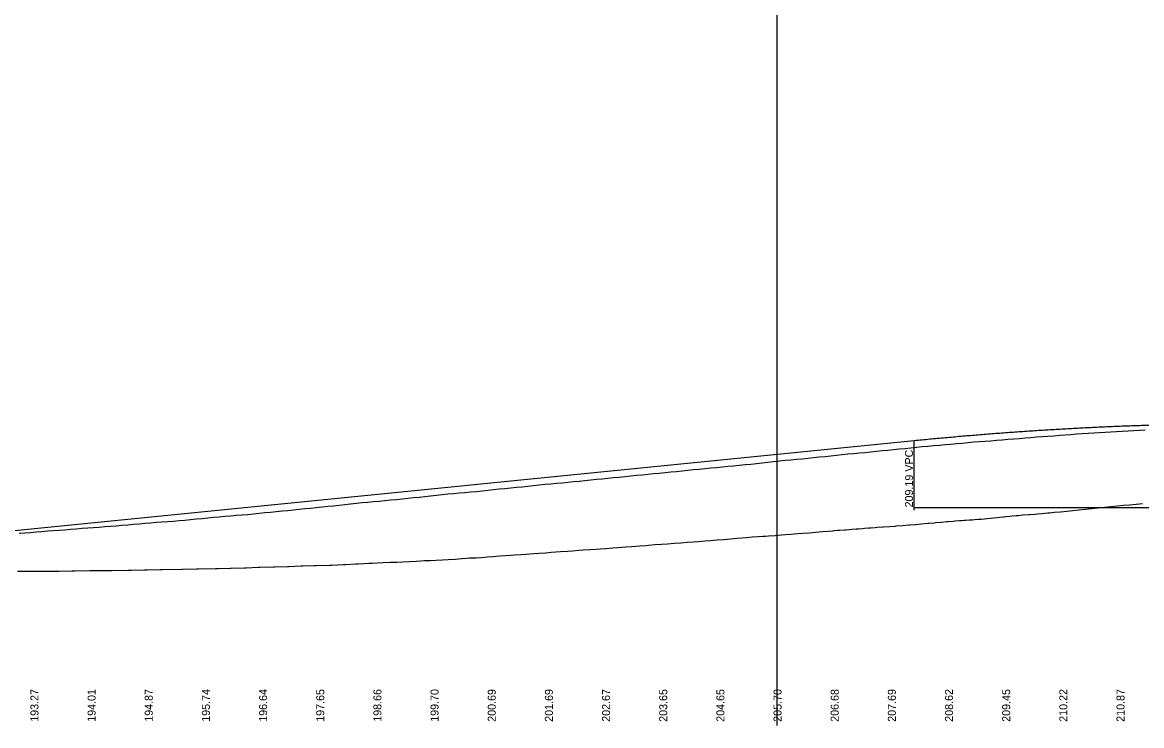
# Model space of a CAD drawing. Extents: x 1838386 to 1955906, y 719739 to 834437.
# Drawn here: x 1880098 to 1881077, y 820597 to 821212 of the extents above; entities that cross this region are included whole.
import ezdxf

# ---------------------------------------------------------------- set-up
doc = ezdxf.new("R2010")
doc.units = 0
for name, color, linetype in [('RD_DDB_Profile_EX', 7, 'Continuous'), ('RD_DDB_Profile_PR', 7, 'Continuous'), ('RD_DDB_StripGrade', 7, 'Continuous'), ('RD_DDB_VCLbl', 7, 'Continuous'), ('RD_Sketch1', 7, 'Continuous')]:
    doc.layers.add(name, color=color, linetype=linetype)

msp = doc.modelspace()

# ---------------------------------------------------------------- linework, layer by layer
at = {"layer": 'RD_DDB_Profile_EX'}
for points in [[(1880890.15, 820841.17), (1880895.15, 820841.68), (1880900.15, 820842.15), (1880905.15, 820842.53), (1880910.15, 820842.97), (1880915.15, 820843.44), (1880920.15, 820843.9), (1880925.15, 820844.37), (1880930.15, 820844.82), (1880935.15, 820845.12), (1880940.15, 820845.5), (1880945.15, 820845.91), (1880950.15, 820846.31), (1880955.15, 820846.72), (1880960.15, 820847.14), (1880965.15, 820847.57), (1880970.15, 820847.99), (1880975.15, 820848.37), (1880980.15, 820848.78), (1880985.15, 820849.2), (1880990.15, 820849.58), (1880995.15, 820849.94), (1881000.15, 820850.31), (1881005.15, 820850.69), (1881010.15, 820851.05), (1881015.15, 820851.38), (1881020.15, 820851.82), (1881025.15, 820852.16), (1881030.15, 820852.46), (1881035.15, 820852.75), (1881040.15, 820853.06), (1881045.15, 820853.38), (1881050.15, 820853.72), (1881055.15, 820854.04), (1881060.15, 820854.29), (1881065.15, 820854.57), (1881070.15, 820854.91), (1881075.15, 820855.23), (1881080.15, 820855.49)], [(1880390.15, 820791.24), (1880395.15, 820791.81), (1880400.15, 820792.29), (1880405.15, 820792.69), (1880410.15, 820793.14), (1880415.15, 820793.65), (1880420.15, 820794.18), (1880425.15, 820794.64), (1880430.15, 820795.15), (1880435.15, 820795.69), (1880440.15, 820796.18), (1880445.15, 820796.67), (1880450.15, 820797.2), (1880455.15, 820797.75), (1880460.15, 820798.29), (1880465.15, 820798.83), (1880470.15, 820799.36), (1880475.15, 820799.82), (1880480.15, 820800.24), (1880485.15, 820800.68), (1880490.15, 820801.15), (1880495.15, 820801.65), (1880500.15, 820802.2), (1880505.15, 820802.76), (1880510.15, 820803.28), (1880515.15, 820803.79), (1880520.15, 820804.25), (1880525.15, 820804.74), (1880530.15, 820805.22), (1880535.15, 820805.71), (1880540.15, 820806.23), (1880545.15, 820806.81), (1880550.15, 820807.35), (1880555.15, 820807.84), (1880560.15, 820808.3), (1880565.15, 820808.73), (1880570.15, 820809.23), (1880575.15, 820809.71), (1880580.15, 820810.19), (1880585.15, 820810.67), (1880590.15, 820811.19), (1880595.15, 820811.72), (1880600.15, 820812.18), (1880605.15, 820812.63), (1880610.15, 820813.18), (1880615.15, 820813.71), (1880620.15, 820814.16), (1880625.15, 820814.64), (1880630.15, 820815.16), (1880635.15, 820815.69), (1880640.15, 820816.2), (1880645.15, 820816.68), (1880650.15, 820817.16), (1880655.15, 820817.62), (1880660.15, 820818.12), (1880665.15, 820818.59), (1880670.15, 820819.1), (1880675.15, 820819.7), (1880680.15, 820820.28), (1880685.15, 820820.82), (1880690.15, 820821.18), (1880695.15, 820821.59), (1880700.15, 820822.15), (1880705.15, 820822.63), (1880710.15, 820823.13), (1880715.15, 820823.58), (1880720.15, 820824.07), (1880725.15, 820824.54), (1880730.15, 820825.08), (1880735.15, 820825.53), (1880740.15, 820826.04), (1880745.15, 820826.62), (1880750.15, 820827.13), (1880755.15, 820827.65), (1880760.15, 820828.26), (1880765.15, 820828.84), (1880770.15, 820829.32), (1880775.15, 820829.66), (1880780.15, 820830.21), (1880785.15, 820830.71), (1880790.15, 820831.21), (1880795.15, 820831.71), (1880800.15, 820832.21), (1880805.15, 820832.71), (1880810.15, 820833.2), (1880815.15, 820833.74), (1880820.15, 820834.32), (1880825.15, 820834.79), (1880830.15, 820835.24), (1880835.15, 820835.74), (1880840.15, 820836.25), (1880845.15, 820836.74), (1880850.15, 820837.24), (1880855.15, 820837.76), (1880860.15, 820838.27), (1880865.15, 820838.78), (1880870.15, 820839.25), (1880875.15, 820839.72), (1880880.15, 820840.22), (1880885.15, 820840.73), (1880890.15, 820841.17)], [(1880095.15, 820764.97), (1880100.15, 820765.39), (1880105.15, 820765.8), (1880110.15, 820766.25), (1880115.15, 820766.62), (1880120.15, 820766.97), (1880125.15, 820767.36), (1880130.15, 820767.74), (1880135.15, 820768.12), (1880140.15, 820768.56), (1880145.15, 820768.99), (1880150.15, 820769.34), (1880155.15, 820769.62), (1880160.15, 820769.92), (1880165.15, 820770.34), (1880170.15, 820770.76), (1880175.15, 820771.13), (1880180.15, 820771.55), (1880185.15, 820772.04), (1880190.15, 820772.49), (1880195.15, 820772.9), (1880200.15, 820773.3), (1880205.15, 820773.77), (1880210.15, 820774.24), (1880215.15, 820774.64), (1880220.15, 820775.01), (1880225.15, 820775.32), (1880230.15, 820775.65), (1880235.15, 820776.06), (1880240.15, 820776.51), (1880245.15, 820777.01), (1880250.15, 820777.53), (1880255.15, 820778.04), (1880260.15, 820778.55), (1880265.15, 820779.02), (1880270.15, 820779.48), (1880275.15, 820779.91), (1880280.15, 820780.29), (1880285.15, 820780.68), (1880290.15, 820781.08), (1880295.15, 820781.52), (1880300.15, 820782.01), (1880305.15, 820782.51), (1880310.15, 820783.01), (1880315.15, 820783.51), (1880320.15, 820784.01), (1880325.15, 820784.5), (1880330.15, 820785), (1880335.15, 820785.5), (1880340.15, 820786.01), (1880345.15, 820786.53), (1880350.15, 820787.04), (1880355.15, 820787.55), (1880360.15, 820788.06), (1880365.15, 820788.56), (1880370.15, 820789.07), (1880375.15, 820789.58), (1880380.15, 820790.09), (1880385.15, 820790.67), (1880390.15, 820791.24)]]:
    msp.add_lwpolyline(points, dxfattribs=at)
at = {"layer": 'RD_DDB_Profile_PR'}
msp.add_line((1880091.08, 820767.49), (1880878.08, 820846.1), dxfattribs=at)
msp.add_spline([(1880878.08, 820846.1), (1880891.68, 820847.42), (1880905.28, 820848.69), (1880918.88, 820849.9), (1880932.48, 820851.04), (1880946.08, 820852.12), (1880959.68, 820853.15), (1880973.28, 820854.11), (1880986.88, 820855.01), (1881000.48, 820855.85), (1881014.08, 820856.62), (1881027.68, 820857.34), (1881041.28, 820858), (1881054.88, 820858.59), (1881068.48, 820859.12), (1881082.08, 820859.59), (1881095.68, 820860.01), (1881109.28, 820860.36), (1881122.88, 820860.64), (1881136.48, 820860.87), (1881150.08, 820861.04), (1881163.68, 820861.14), (1881177.28, 820861.19), (1881190.88, 820861.17), (1881204.48, 820861.09), (1881218.08, 820860.95), (1881231.68, 820860.75), (1881245.28, 820860.49), (1881258.88, 820860.17), (1881272.48, 820859.78), (1881286.08, 820859.34), (1881299.68, 820858.83), (1881313.28, 820858.26), (1881326.88, 820857.64), (1881340.48, 820856.95), (1881354.08, 820856.2), (1881367.68, 820855.38), (1881381.28, 820854.51), (1881394.88, 820853.58), (1881408.48, 820852.58), (1881422.08, 820851.53), (1881435.68, 820850.41), (1881449.28, 820849.23), (1881462.88, 820847.99), (1881476.48, 820846.69), (1881490.08, 820845.33), (1881503.68, 820843.9), (1881517.28, 820842.42), (1881530.88, 820840.88), (1881544.48, 820839.27), (1881558.08, 820837.6)], degree=3, dxfattribs=at)
at = {"layer": 'RD_DDB_VCLbl'}
for p, q in [((1880878.08, 820785.1), (1880878.08, 820846.1)), ((1880878.08, 820787.6), (1881558.08, 820787.6))]:
    msp.add_line(p, q, dxfattribs=at)
at = {"layer": 'RD_Sketch1'}
msp.add_line((1880758.32, 820596.8), (1880758.32, 821674.78), dxfattribs=at)
msp.add_line((1880758.32, 820596.8), (1880758.32, 821674.78), dxfattribs=at)
msp.add_line((1880758.32, 820596.8), (1880758.32, 821674.78), dxfattribs=at)
msp.add_lwpolyline([(1880093.9, 820731.71), (1880106.12, 820731.85), (1880110.27, 820731.86), (1880121.99, 820731.93), (1880125.85, 820731.96), (1880129.95, 820731.96), (1880141.66, 820732.06), (1880144.02, 820732.17), (1880157.16, 820732.33), (1880160.61, 820732.34), (1880173.32, 820732.52), (1880176.21, 820732.55), (1880190.66, 820732.7), (1880193.26, 820732.73), (1880204.93, 820732.9), (1880207.05, 820732.94), (1880218.56, 820733.18), (1880220.54, 820733.22), (1880237.61, 820733.63), (1880237.91, 820733.64), (1880238.21, 820733.65), (1880250.3, 820733.85), (1880252.1, 820733.88), (1880252.14, 820733.88), (1880267.08, 820734.19), (1880267.24, 820734.19), (1880267.39, 820734.2), (1880269.37, 820734.22), (1880279.79, 820734.39), (1880280.48, 820734.41), (1880292.37, 820734.84), (1880293.65, 820734.86), (1880304.65, 820735.2), (1880305.62, 820735.23), (1880317.6, 820735.49), (1880318.83, 820735.53), (1880329.89, 820735.92), (1880331.08, 820735.95), (1880341.86, 820736.37), (1880343.31, 820736.39), (1880353.3, 820736.74), (1880355, 820736.79), (1880366.56, 820737.16), (1880368.44, 820737.22), (1880378.91, 820737.66), (1880380.63, 820737.73), (1880389.68, 820738.22), (1880391.63, 820738.35), (1880401.24, 820738.77), (1880402.43, 820738.81), (1880404.07, 820738.88), (1880413.65, 820739.29), (1880419.74, 820739.57), (1880425.5, 820739.85), (1880430.88, 820740.11), (1880436.69, 820740.41), (1880442.59, 820740.69), (1880446.45, 820740.85), (1880449.73, 820741.07), (1880455.12, 820741.31), (1880459.96, 820741.54), (1880465.63, 820741.88), (1880470.49, 820742.12), (1880476.72, 820742.48), (1880482.31, 820742.86), (1880486.48, 820743.17), (1880489.23, 820743.37), (1880494.93, 820743.63), (1880499.63, 820743.93), (1880505.01, 820744.36), (1880509.66, 820744.76), (1880515.61, 820745.12), (1880520.64, 820745.46), (1880525.38, 820745.83), (1880528.37, 820746.05), (1880534.09, 820746.46), (1880538.72, 820746.75), (1880545.26, 820747.24), (1880550.07, 820747.59), (1880555.83, 820748.01), (1880560.61, 820748.34), (1880564.71, 820748.67), (1880568.63, 820749), (1880574.75, 820749.41), (1880579.29, 820749.69), (1880584.75, 820750.1), (1880588.33, 820750.36), (1880594.87, 820750.73), (1880599.56, 820751.06), (1880603.54, 820751.34), (1880608.27, 820751.64), (1880614.49, 820752.14), (1880618.89, 820752.45), (1880625.98, 820753.03), (1880631.17, 820753.45), (1880638.08, 820753.97), (1880643.53, 820754.41), (1880645.85, 820754.62), (1880651.34, 820755.05), (1880657.13, 820755.47), (1880662.36, 820755.82), (1880668.36, 820756.24), (1880674.02, 820756.71), (1880679.61, 820757.13), (1880684.84, 820757.53), (1880689.31, 820757.9), (1880695.12, 820758.36), (1880699.98, 820758.71), (1880705.81, 820759.18), (1880711.29, 820759.63), (1880717.69, 820760.23), (1880722.91, 820760.61), (1880727.32, 820760.97), (1880731.07, 820761.29), (1880736.75, 820761.74), (1880741.32, 820762.1), (1880745.81, 820762.48), (1880748.05, 820762.59), (1880750.63, 820762.63), (1880756.51, 820763.15), (1880761.95, 820763.54), (1880765.57, 820763.84), (1880770.16, 820764.26), (1880776.02, 820764.67), (1880780.59, 820765.01), (1880786.59, 820765.49), (1880791.79, 820765.91), (1880797.8, 820766.45), (1880803.11, 820766.86), (1880807.14, 820767.24), (1880808.1, 820767.33), (1880811.2, 820767.59), (1880812.69, 820767.7), (1880817.35, 820768.02), (1880818.21, 820768.09), (1880821.62, 820768.33), (1880823.72, 820768.5), (1880827.29, 820768.79), (1880829.26, 820768.93), (1880833.03, 820769.19), (1880834.76, 820769.34), (1880838.44, 820769.66), (1880840.28, 820769.83), (1880844.03, 820770.16), (1880845.83, 820770.29), (1880850.7, 820770.63), (1880851.37, 820770.67), (1880856.73, 820770.96), (1880856.88, 820770.97), (1880861.44, 820771.26), (1880862.37, 820771.34), (1880867.74, 820771.83), (1880867.92, 820771.85), (1880873.44, 820772.25), (1880874.22, 820772.31), (1880878.95, 820772.69), (1880879.47, 820772.73), (1880884.35, 820773.23), (1880884.47, 820773.24), (1880889.99, 820773.73), (1880891.04, 820773.82), (1880895.53, 820774.19), (1880896.64, 820774.27), (1880901.05, 820774.63), (1880901.79, 820774.69), (1880906.55, 820775.17), (1880907.71, 820775.29), (1880912.09, 820775.65), (1880913.58, 820775.77), (1880917.62, 820776.08), (1880919.59, 820776.23), (1880921.78, 820776.35), (1880923.16, 820776.44), (1880926.54, 820776.67), (1880928.68, 820776.81), (1880930.9, 820776.95), (1880934.18, 820777.23), (1880936.56, 820777.43), (1880939.7, 820777.72), (1880941.58, 820777.9), (1880945.21, 820778.27), (1880947.46, 820778.51), (1880950.73, 820778.84), (1880953.13, 820779.08), (1880956.25, 820779.41), (1880958.17, 820779.61), (1880961.78, 820779.96), (1880963.82, 820780.16), (1880967.31, 820780.47), (1880969.05, 820780.63), (1880972.84, 820780.98), (1880973.24, 820781.02), (1880978.38, 820781.41), (1880979.15, 820781.46), (1880983.9, 820781.83), (1880986.04, 820782), (1880989.42, 820782.28), (1880992.36, 820782.52), (1880994.93, 820782.76), (1880996.59, 820782.91), (1881000.44, 820783.3), (1881005.97, 820783.85), (1881011.49, 820784.4), (1881017.01, 820784.95), (1881022.54, 820785.5), (1881028.06, 820786.05), (1881033.22, 820786.56), (1881033.58, 820786.59), (1881039.1, 820787.16), (1881044.63, 820787.73), (1881050.15, 820788.29), (1881055.67, 820788.86), (1881061.2, 820789.42), (1881066.72, 820789.98), (1881072.24, 820790.54), (1881072.6, 820790.57), (1881077.77, 820791.1)], dxfattribs=at)
msp.add_lwpolyline([(1880093.9, 820731.71), (1880106.12, 820731.85), (1880110.27, 820731.86), (1880121.99, 820731.93), (1880125.85, 820731.96), (1880129.95, 820731.96), (1880141.66, 820732.06), (1880144.02, 820732.17), (1880157.16, 820732.33), (1880160.61, 820732.34), (1880173.32, 820732.52), (1880176.21, 820732.55), (1880190.66, 820732.7), (1880193.26, 820732.73), (1880204.93, 820732.9), (1880207.05, 820732.94), (1880218.56, 820733.18), (1880220.54, 820733.22), (1880237.61, 820733.63), (1880237.91, 820733.64), (1880238.21, 820733.65), (1880250.3, 820733.85), (1880252.1, 820733.88), (1880252.14, 820733.88), (1880267.08, 820734.19), (1880267.24, 820734.19), (1880267.39, 820734.2), (1880269.37, 820734.22), (1880279.79, 820734.39), (1880280.48, 820734.41), (1880292.37, 820734.84), (1880293.65, 820734.86), (1880304.65, 820735.2), (1880305.62, 820735.23), (1880317.6, 820735.49), (1880318.83, 820735.53), (1880329.89, 820735.92), (1880331.08, 820735.95), (1880341.86, 820736.37), (1880343.31, 820736.39), (1880353.3, 820736.74), (1880355, 820736.79), (1880366.56, 820737.16), (1880368.44, 820737.22), (1880378.91, 820737.66), (1880380.63, 820737.73), (1880389.68, 820738.22), (1880391.63, 820738.35), (1880401.24, 820738.77), (1880402.43, 820738.81), (1880404.07, 820738.88), (1880413.65, 820739.29), (1880419.74, 820739.57), (1880425.5, 820739.85), (1880430.88, 820740.11), (1880436.69, 820740.41), (1880442.59, 820740.69), (1880446.45, 820740.85), (1880449.73, 820741.07), (1880455.12, 820741.31), (1880459.96, 820741.54), (1880465.63, 820741.88), (1880470.49, 820742.12), (1880476.72, 820742.48), (1880482.31, 820742.86), (1880486.48, 820743.17), (1880489.23, 820743.37), (1880494.93, 820743.63), (1880499.63, 820743.93), (1880505.01, 820744.36), (1880509.66, 820744.76), (1880515.61, 820745.12), (1880520.64, 820745.46), (1880525.38, 820745.83), (1880528.37, 820746.05), (1880534.09, 820746.46), (1880538.72, 820746.75), (1880545.26, 820747.24), (1880550.07, 820747.59), (1880555.83, 820748.01), (1880560.61, 820748.34), (1880564.71, 820748.67), (1880568.63, 820749), (1880574.75, 820749.41), (1880579.29, 820749.69), (1880584.75, 820750.1), (1880588.33, 820750.36), (1880594.87, 820750.73), (1880599.56, 820751.06), (1880603.54, 820751.34), (1880608.27, 820751.64), (1880614.49, 820752.14), (1880618.89, 820752.45), (1880625.98, 820753.03), (1880631.17, 820753.45), (1880638.08, 820753.97), (1880643.53, 820754.41), (1880645.85, 820754.62), (1880651.34, 820755.05), (1880657.13, 820755.47), (1880662.36, 820755.82), (1880668.36, 820756.24), (1880674.02, 820756.71), (1880679.61, 820757.13), (1880684.84, 820757.53), (1880689.31, 820757.9), (1880695.12, 820758.36), (1880699.98, 820758.71), (1880705.81, 820759.18), (1880711.29, 820759.63), (1880717.69, 820760.23), (1880722.91, 820760.61), (1880727.32, 820760.97), (1880731.07, 820761.29), (1880736.75, 820761.74), (1880741.32, 820762.1), (1880745.81, 820762.48), (1880748.05, 820762.59), (1880750.63, 820762.63), (1880756.51, 820763.15), (1880761.95, 820763.54), (1880765.57, 820763.84), (1880770.16, 820764.26), (1880776.02, 820764.67), (1880780.59, 820765.01), (1880786.59, 820765.49), (1880791.79, 820765.91), (1880797.8, 820766.45), (1880803.11, 820766.86), (1880807.14, 820767.24), (1880808.1, 820767.33), (1880811.2, 820767.59), (1880812.69, 820767.7), (1880817.35, 820768.02), (1880818.21, 820768.09), (1880821.62, 820768.33), (1880823.72, 820768.5), (1880827.29, 820768.79), (1880829.26, 820768.93), (1880833.03, 820769.19), (1880834.76, 820769.34), (1880838.44, 820769.66), (1880840.28, 820769.83), (1880844.03, 820770.16), (1880845.83, 820770.29), (1880850.7, 820770.63), (1880851.37, 820770.67), (1880856.73, 820770.96), (1880856.88, 820770.97), (1880861.44, 820771.26), (1880862.37, 820771.34), (1880867.74, 820771.83), (1880867.92, 820771.85), (1880873.44, 820772.25), (1880874.22, 820772.31), (1880878.95, 820772.69), (1880879.47, 820772.73), (1880884.35, 820773.23), (1880884.47, 820773.24), (1880889.99, 820773.73), (1880891.04, 820773.82), (1880895.53, 820774.19), (1880896.64, 820774.27), (1880901.05, 820774.63), (1880901.79, 820774.69), (1880906.55, 820775.17), (1880907.71, 820775.29), (1880912.09, 820775.65), (1880913.58, 820775.77), (1880917.62, 820776.08), (1880919.59, 820776.23), (1880921.78, 820776.35), (1880923.16, 820776.44), (1880926.54, 820776.67), (1880928.68, 820776.81), (1880930.9, 820776.95), (1880934.18, 820777.23), (1880936.56, 820777.43), (1880939.7, 820777.72), (1880941.58, 820777.9), (1880945.21, 820778.27), (1880947.46, 820778.51), (1880950.73, 820778.84), (1880953.13, 820779.08), (1880956.25, 820779.41), (1880958.17, 820779.61), (1880961.78, 820779.96), (1880963.82, 820780.16), (1880967.31, 820780.47), (1880969.05, 820780.63), (1880972.84, 820780.98), (1880973.24, 820781.02), (1880978.38, 820781.41), (1880979.15, 820781.46), (1880983.9, 820781.83), (1880986.04, 820782), (1880989.42, 820782.28), (1880992.36, 820782.52), (1880994.93, 820782.76), (1880996.59, 820782.91), (1881000.44, 820783.3), (1881005.97, 820783.85), (1881011.49, 820784.4), (1881017.01, 820784.95), (1881022.54, 820785.5), (1881028.06, 820786.05), (1881033.22, 820786.56), (1881033.58, 820786.59), (1881039.1, 820787.16), (1881044.63, 820787.73), (1881050.15, 820788.29), (1881055.67, 820788.86), (1881061.2, 820789.42), (1881066.72, 820789.98), (1881072.24, 820790.54), (1881072.6, 820790.57), (1881077.77, 820791.1)], dxfattribs=at)
msp.add_lwpolyline([(1880093.9, 820731.71), (1880106.12, 820731.85), (1880110.27, 820731.86), (1880121.99, 820731.93), (1880125.85, 820731.96), (1880129.95, 820731.96), (1880141.66, 820732.06), (1880144.02, 820732.17), (1880157.16, 820732.33), (1880160.61, 820732.34), (1880173.32, 820732.52), (1880176.21, 820732.55), (1880190.66, 820732.7), (1880193.26, 820732.73), (1880204.93, 820732.9), (1880207.05, 820732.94), (1880218.56, 820733.18), (1880220.54, 820733.22), (1880237.61, 820733.63), (1880237.91, 820733.64), (1880238.21, 820733.65), (1880250.3, 820733.85), (1880252.1, 820733.88), (1880252.14, 820733.88), (1880267.08, 820734.19), (1880267.24, 820734.19), (1880267.39, 820734.2), (1880269.37, 820734.22), (1880279.79, 820734.39), (1880280.48, 820734.41), (1880292.37, 820734.84), (1880293.65, 820734.86), (1880304.65, 820735.2), (1880305.62, 820735.23), (1880317.6, 820735.49), (1880318.83, 820735.53), (1880329.89, 820735.92), (1880331.08, 820735.95), (1880341.86, 820736.37), (1880343.31, 820736.39), (1880353.3, 820736.74), (1880355, 820736.79), (1880366.56, 820737.16), (1880368.44, 820737.22), (1880378.91, 820737.66), (1880380.63, 820737.73), (1880389.68, 820738.22), (1880391.63, 820738.35), (1880401.24, 820738.77), (1880402.43, 820738.81), (1880404.07, 820738.88), (1880413.65, 820739.29), (1880419.74, 820739.57), (1880425.5, 820739.85), (1880430.88, 820740.11), (1880436.69, 820740.41), (1880442.59, 820740.69), (1880446.45, 820740.85), (1880449.73, 820741.07), (1880455.12, 820741.31), (1880459.96, 820741.54), (1880465.63, 820741.88), (1880470.49, 820742.12), (1880476.72, 820742.48), (1880482.31, 820742.86), (1880486.48, 820743.17), (1880489.23, 820743.37), (1880494.93, 820743.63), (1880499.63, 820743.93), (1880505.01, 820744.36), (1880509.66, 820744.76), (1880515.61, 820745.12), (1880520.64, 820745.46), (1880525.38, 820745.83), (1880528.37, 820746.05), (1880534.09, 820746.46), (1880538.72, 820746.75), (1880545.26, 820747.24), (1880550.07, 820747.59), (1880555.83, 820748.01), (1880560.61, 820748.34), (1880564.71, 820748.67), (1880568.63, 820749), (1880574.75, 820749.41), (1880579.29, 820749.69), (1880584.75, 820750.1), (1880588.33, 820750.36), (1880594.87, 820750.73), (1880599.56, 820751.06), (1880603.54, 820751.34), (1880608.27, 820751.64), (1880614.49, 820752.14), (1880618.89, 820752.45), (1880625.98, 820753.03), (1880631.17, 820753.45), (1880638.08, 820753.97), (1880643.53, 820754.41), (1880645.85, 820754.62), (1880651.34, 820755.05), (1880657.13, 820755.47), (1880662.36, 820755.82), (1880668.36, 820756.24), (1880674.02, 820756.71), (1880679.61, 820757.13), (1880684.84, 820757.53), (1880689.31, 820757.9), (1880695.12, 820758.36), (1880699.98, 820758.71), (1880705.81, 820759.18), (1880711.29, 820759.63), (1880717.69, 820760.23), (1880722.91, 820760.61), (1880727.32, 820760.97), (1880731.07, 820761.29), (1880736.75, 820761.74), (1880741.32, 820762.1), (1880745.81, 820762.48), (1880748.05, 820762.59), (1880750.63, 820762.63), (1880756.51, 820763.15), (1880761.95, 820763.54), (1880765.57, 820763.84), (1880770.16, 820764.26), (1880776.02, 820764.67), (1880780.59, 820765.01), (1880786.59, 820765.49), (1880791.79, 820765.91), (1880797.8, 820766.45), (1880803.11, 820766.86), (1880807.14, 820767.24), (1880808.1, 820767.33), (1880811.2, 820767.59), (1880812.69, 820767.7), (1880817.35, 820768.02), (1880818.21, 820768.09), (1880821.62, 820768.33), (1880823.72, 820768.5), (1880827.29, 820768.79), (1880829.26, 820768.93), (1880833.03, 820769.19), (1880834.76, 820769.34), (1880838.44, 820769.66), (1880840.28, 820769.83), (1880844.03, 820770.16), (1880845.83, 820770.29), (1880850.7, 820770.63), (1880851.37, 820770.67), (1880856.73, 820770.96), (1880856.88, 820770.97), (1880861.44, 820771.26), (1880862.37, 820771.34), (1880867.74, 820771.83), (1880867.92, 820771.85), (1880873.44, 820772.25), (1880874.22, 820772.31), (1880878.95, 820772.69), (1880879.47, 820772.73), (1880884.35, 820773.23), (1880884.47, 820773.24), (1880889.99, 820773.73), (1880891.04, 820773.82), (1880895.53, 820774.19), (1880896.64, 820774.27), (1880901.05, 820774.63), (1880901.79, 820774.69), (1880906.55, 820775.17), (1880907.71, 820775.29), (1880912.09, 820775.65), (1880913.58, 820775.77), (1880917.62, 820776.08), (1880919.59, 820776.23), (1880921.78, 820776.35), (1880923.16, 820776.44), (1880926.54, 820776.67), (1880928.68, 820776.81), (1880930.9, 820776.95), (1880934.18, 820777.23), (1880936.56, 820777.43), (1880939.7, 820777.72), (1880941.58, 820777.9), (1880945.21, 820778.27), (1880947.46, 820778.51), (1880950.73, 820778.84), (1880953.13, 820779.08), (1880956.25, 820779.41), (1880958.17, 820779.61), (1880961.78, 820779.96), (1880963.82, 820780.16), (1880967.31, 820780.47), (1880969.05, 820780.63), (1880972.84, 820780.98), (1880973.24, 820781.02), (1880978.38, 820781.41), (1880979.15, 820781.46), (1880983.9, 820781.83), (1880986.04, 820782), (1880989.42, 820782.28), (1880992.36, 820782.52), (1880994.93, 820782.76), (1880996.59, 820782.91), (1881000.44, 820783.3), (1881005.97, 820783.85), (1881011.49, 820784.4), (1881017.01, 820784.95), (1881022.54, 820785.5), (1881028.06, 820786.05), (1881033.22, 820786.56), (1881033.58, 820786.59), (1881039.1, 820787.16), (1881044.63, 820787.73), (1881050.15, 820788.29), (1881055.67, 820788.86), (1881061.2, 820789.42), (1881066.72, 820789.98), (1881072.24, 820790.54), (1881072.6, 820790.57), (1881077.77, 820791.1)], dxfattribs=at)

# ---------------------------------------------------------------- texts
at = {"layer": 'RD_DDB_StripGrade'}
for s, p in [('209.19 VPC', (1880877.08, 820787.6)), ('193.27', (1880112.08, 820600.13)), ('194.01', (1880162.08, 820600.13)), ('194.87', (1880212.08, 820600.13)), ('195.74', (1880262.08, 820600.13)), ('196.64', (1880312.08, 820600.13)), ('197.65', (1880362.08, 820600.13)), ('198.66', (1880412.08, 820600.13)), ('199.70', (1880462.08, 820600.13)), ('200.69', (1880512.08, 820600.13)), ('201.69', (1880562.08, 820600.13)), ('202.67', (1880612.08, 820600.13)), ('203.65', (1880662.08, 820600.13)), ('204.65', (1880712.08, 820600.13)), ('205.70', (1880762.08, 820600.13)), ('206.68', (1880812.08, 820600.13)), ('207.69', (1880862.08, 820600.13)), ('208.62', (1880912.08, 820600.13)), ('209.45', (1880962.08, 820600.13)), ('210.22', (1881012.08, 820600.13)), ('210.87', (1881062.08, 820600.13))]:
    msp.add_text(s, height=7, rotation=90, dxfattribs=at).set_placement(p)

doc.saveas('drawing.dxf')
